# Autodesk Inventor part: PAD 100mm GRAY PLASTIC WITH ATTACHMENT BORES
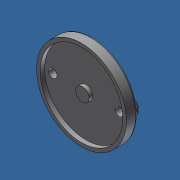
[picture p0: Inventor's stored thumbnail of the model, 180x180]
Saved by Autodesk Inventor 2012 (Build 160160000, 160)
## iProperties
Created: 2007-03
Part Number: PAD 100mm GRAY PLASTIC WITH ATTACHMENT BORES
Document SubType Name: Modeling
Designer: Andy Moles
Material: ABS Plastic
Density: 1.06 g/cm^3
Mass: 89.8977 g
Surface Area: 225.374 cm^2
Volume: 84.8091 cm^3
Author: Andy Moles
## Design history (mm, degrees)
sketch "Sketch1"
  geometry: L1 (0, 0)-(50, 0); L2 (50, 0)-(50, 10.335); L3 (0, 0)-(0, 19); L4 (6.633, 19)-(11.817, 19); L5 (48.362, 12.302)-(12.18, 18.967); L6 (0, 0)-(0, 8); A1 r 7.5 centre (0, 15.5) between (0, 8) and (6.633, 19); A2 r 2 centre (11.817, 17) between (12.18, 18.967) and (11.817, 19); A3 r 2 centre (48, 10.335) between (50, 10.335) and (48.362, 12.302); 2 further points
  constraints: 12 end point, 6 point on circle, 6 point on line, 4 tangent, 3 centre point, 2 perpendicular, 1 collinear, 1 equal radius, 1 horizontal, 1 parallel
  dimensions: "d0" = 50 distance of L1.start L1.end; "d1" = 12 distance of L1.end point (50, 12); "d2" = 19 distance of L1.start L3.end; "d3" = 15 diameter of A1; "d4" = 3.5 distance of A1.centre L3.end; "d5" = 12 horizontal distance of point (12, 19) L1.start; "d6" = 2 radius of A2; "d14" = 19 distance between parallel lines of L4 L1
revolve "Revolution1" sketch "Sketch1" stored, may be unused: angle "d7" = 90 deg
sketch "Sketch2"
  geometry: C1 r 50 at (0, 0) reference; C2 r 7.5 at (0, 0)
  constraints: 1 centre point, 1 coincident
  dimensions: "d8" = 15 diameter of C2
extrude "Extrusion1" cut sketch "Sketch2" distance "d9" = 1; taper "d10" = 0 deg
sketch "Sketch3"
  geometry: C1 r 7.5 at (0, 0) reference; C2 r 50 at (0, 0) reference; C3 r 46 at (0, 0)
  constraints: 1 centre point, 1 coincident
  dimensions: "d11" = 4 radial gap between concentric circles of C2 C3
extrude "Extrusion2" cut sketch "Sketch3" distance "d12" = 5; taper "d13" = 0 deg
sketch "HOLES OUT"
  geometry: L1 (12, 10)-(12, -10); L2 (-12, 10)-(-12, -10); L3 (-37, 10)-(-12, 10); L4 (-37, -10)-(-12, -10); L5 (12, 10)-(37, 10); L6 (12, -10)-(37, -10); C1 r 7.5 at (0, 0) reference; A1 r 10 centre (-37, 0) between (-37, 10) and (-37, -10); A2 r 10 centre (37, 0) between (37, -10) and (37, 10); 2 further points
  constraints: 12 end point, 4 horizontal alignment, 4 point on circle, 3 parallel, 2 centre point, 2 midpoint, 1 perpendicular, 1 tangent, 1 vertical
  dimensions: "d15" = 20 diameter of A1; "d16" = 20 diameter of A2; "d17" = 74 distance of A2.centre A1.centre; "d18" = 37 distance of C1.centre A1.centre (= 0.5 x d17); "d19" = 20 distance of L2.start L2.end; "d20" = 20 distance of L1.start L1.end; "d21" = 25 distance from line of L2 A1.centre; "d22" = 25 distance from line of L1 A2.centre (= d21)
extrude "Extrusion3" join sketch "HOLES OUT" distance "d23" = 13; taper "d24" = 0 deg
fillet "Fillet1" dims "d25" = 2
sketch "Sketch5"
  geometry: C1 r 4.75 at (-37, 0); C2 r 4.75 at (37, 0); A1 r 10 centre (-37, 0) between (-37, 10) and (-37, -10) reference; 1 further point
  constraints: 2 centre point, 2 coincident
  dimensions: "d26" = 9.5 diameter of C1; "d27" = 9.5 diameter of C2
extrude "Extrusion4" cut sketch "Sketch5" distance "d28" = 12.7; taper "d29" = 0 deg
sketch "Sketch6"
  geometry: C1 r 4.75 at (-37, 0) reference; C2 r 4.75 at (37, 0) reference
extrude "HOLE KNOCK OUT" cut sketch "Sketch6" distance "d30" = 10; taper "d31" = 0 deg
body "Solid1"
